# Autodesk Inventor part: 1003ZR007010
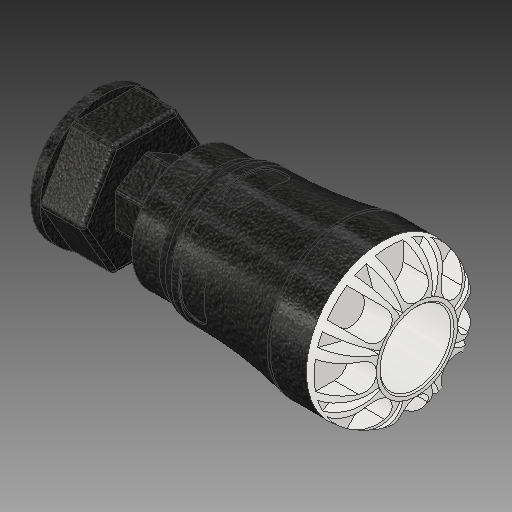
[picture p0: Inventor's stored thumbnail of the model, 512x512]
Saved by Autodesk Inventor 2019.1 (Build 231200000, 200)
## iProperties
Created: 2016-12
Part Number: 1003ZR007010
Material: PVC-Piping
Description: PLASSON FEMALE ADAPTOR WITH FREE NUT 3/4''CTS x 1''
Document SubType Name: Modeling
Designer: KIM
Mass: 664.23 g
Surface Area: 733.008 cm^2
Volume: 474.45 cm^3
Density: 1.4 g/cm^3
Appearance: Black Cast
Author: KIM
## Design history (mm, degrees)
derived "1003ZR.ipt"
feature "Solid1::1003ZR.ipt"
feature "Solid2::1003ZR.ipt"
tag "TaggingFeature1"
body "Solid1"
body "Solid2"
other parameters: "d1" = 22.72284, "d2" = 22.1, "d3" = 25.21125, "d4" = 46.99, "d6" = 54.102, "d8" = 39.9415, "d13" = 8.7115, "d14" = 8.7115, "d15" = 0, "d17" = 360 deg, "d19" = 8 deg, "d20" = 0.442, "d21" = 0.442, "d22" = 8 deg, "d24" = 0, "d26" = 360 deg, "d32" = 4.699, "d33" = 4.699, "d39" = 0.55893, "d42" = 18.631, "d43" = 36.6522, "d46" = 1.84167, "d48" = 17.69945, "d50" = 1.34112, "d51" = 0.4699, "d54" = 7.735, "d55" = 4.862, "d57" = 15.18216, "d58" = 0, "d68" = 360 deg, "d72" = 0.442, "d74" = 0, "d76" = 6.57475, "d78" = 70.866, "d79" = 12.7, "d80" = 100.076, "d81" = 3.00228, "d82" = 16.01216, "d83" = 18.631, "d84" = 14.9048, "d85" = 10.0076, "d87" = 13.00988, "d88" = 0, "d90" = 0, "d91" = 1.27, "d_" = 22.1, "E_" = 46.99, "H_" = 100.076, "l_" = 54.102, "G_" = 18.631, "d9" = 10.88937, "d11" = 46.99, "d12" = 25.21125, "d49" = 4.064
